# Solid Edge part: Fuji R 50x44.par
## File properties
Title: Lines R 50x44
Author: DESYS
Template: Parte SCARABEO.par
Last saved by: i.fialdini
Revision: 24
Application: Solid Edge
Tipo di contenuto documento: 0
Precisione: 0.990
Document Number: 6003
Revision: 0
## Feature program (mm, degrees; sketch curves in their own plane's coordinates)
sketch for "unnamed Protrusion 1" plane through (0, 0, 0) normal (0, -1, 0) x-axis (1, 0, 0)
extrude "unnamed Protrusion 1" add finite 140 along -normal
fillet "Rotondo_22" radius 35
lofted cutout "unnamed LoftedCutout 1"
sketch for "unnamed Protrusion 2" plane through (0, 140, 0) normal (0, 1, 0) x-axis (-1, 0, 0)
extrude "unnamed Protrusion 2" add through along -normal
draft "Spoglia_2"  Angles1 = 10 deg
fillet "Rotondo_46" radius 90
fillet "Rotondo_48" radius 5
fillet "Rotondo_50" radius 20
sketch for "unnamed Cutout 1" plane through (0, 0, 0) normal (0, -1, 0) x-axis (-1, 0, 0)
  line (-210, -62.5) -> (-210, -160)
  arc centre (-175, -160) radius 35 from (-175, -195) to (-210, -160) cw
  line (-175, -195) -> (175, -195)
  arc centre (175, -160) radius 35 from (210, -160) to (175, -195) cw
  line (210, -160) -> (210, 140)
  arc centre (175, 140) radius 35 from (175, 175) to (210, 140) cw
  line (175, 175) -> (-175, 175)
  arc centre (-175, 140) radius 35 from (-210, 140) to (-175, 175) cw
  line (-210, 140) -> (-210, 57.5)
  line (-210, 57.5) -> (-218.6603, 42.5)
  line (-218.6603, 42.5) -> (-218.6603, -47.5)
  line (-218.6603, -47.5) -> (-210, -62.5)
  dimension (linear) = 210
  dimension (linear) = 210
  dimension (linear) = 218.6603
extrude "unnamed Cutout 1" cut along +normal
fillet "Rotondo_51" radius 20
fillet "Rotondo_27" radius 10
sketch for "unnamed Protrusion 3" plane through (0, 25, 0) normal (0, -1, 0) x-axis (0, 0, -1)
extrude "unnamed Protrusion 3" add to key point along +normal
sketch for "Foro_9" plane through (0, 45, 0) normal (0, 1, 0) x-axis (-1, 0, 0)
hole "Foro_9" diameter 50 through
sketch for "ProtrusioneEstrusa_8" plane through (0, 0, 0) normal (0, 0, 1) x-axis (1, 0, 0)
extrude "ProtrusioneEstrusa_8" add finite 50 symmetric
fillet "Rotondo_28" radius 10
fillet "Rotondo_29" radius 5
fillet "Rotondo_33" radius 10
fillet "Rotondo_34" radius 5
fillet "Rotondo_35" radius 5
sketch for "unnamed Cutout 2" plane through (0, 67.5, 220) normal (0, 0, 1) x-axis (1, 0, 0)
extrude "unnamed Cutout 2" cut through along -normal
fillet "Rotondo_36" radius 10
fillet "Rotondo_38" radius 5
sketch for "unnamed Cutout 3" #1 plane through (0, 67.5, 220) normal (0, 0, 1) x-axis (1, 0, 0)
sketch for "unnamed Cutout 3" #2 plane through (0, 67.5, 220) normal (0, 0, 1) x-axis (1, 0, 0)
extrude "unnamed Cutout 3" cut through along -normal
sketch for "Foro_10" plane through (0, 67.5, 220) normal (0, 0, 1) x-axis (1, 0, 0)
  hole centre (-200, 42.5) bore radius 7.5
hole "Foro_10" finite
sketch for "unnamed Hole 1" plane through (0, 67.5, 220) normal (0, 0, 1) x-axis (1, 0, 0)
hole "unnamed Hole 1" finite
pattern "unnamed Pattern 1" of "Foro_10", "unnamed Hole 1"
fillet "Rotondo_39" radius 5
sketch for "Foro_12" plane through (0, 140, 0) normal (0, 1, 0) x-axis (-1, 0, 0)
hole "Foro_12" diameter 36 through
fillet "Rotondo_49" radius 2
Other named dimensions: "SuperficieOffset_2": Distance = 20 mm
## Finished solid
Body 1: sheet body, 10 faces, 31 edges, 24 vertices.
  Faces by surface: blend 6, plane 2, cone 1, offset 1
  Edges by curve: intersection 17, circle 9, line 4, curve on surface 1
Body 2: solid body, 156 faces, 356 edges, 201 vertices.
  Faces by surface: cylinder 57, plane 32, blend 31, torus 28, sphere 4, cone 2, offset 1, spline 1
  Edges by curve: circle 161, line 119, intersection 75, curve on surface 1
Bounding box of the edges (mm; curved faces can reach further): 500.000 x 140.000 x 435.000, from (-250, 0, -215) to (250, 140, 220).
Cylindrical faces by radius (mm): R5 x21, R7.5 x2, R10 x16, R18 x1, R20 x4, R25 x1, R35 x11, R109.4231 x1
Conical faces (half-angle, radius in mm at the cone's reference point): 10 deg R25.3038 x2, 10 deg R45 x1
Toroidal faces (ring radius, tube radius in mm): R10 r5 x2, R10 r10 x2, R20 r2 x1, R25 r10 x4, R30 r5 x13, R30 r10 x2, R35 r10 x1, R40 r5 x1, R40.8045 r5 x1, R114.4231 r5 x1
Spherical faces by radius (mm): R5 x4
Planar faces by outward normal: +x 2, +y 4, +z 5, -x 4, -y 10, -z 3, oblique 4
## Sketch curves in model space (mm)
arc centre (0, 31.2658, -204.1392) radius 110 from (0, 45, -95) through (0, 108.0036, -125.3274) to (0, 140, -187.5)
arc centre (0, 31.2658, 204.1392) radius 110 from (0, 45, 95) through (0, 108.0036, 125.3274) to (0, 140, 187.5)
ellipse centre (0, 140, 0) radii 197.5, 187.5
arc centre (-212.5652, 20.9494, 0) radius 120 from (-95, 45, 0) through (-133.6338, 111.3365, 0) to (-197.5, 140, 0)
arc centre (212.5652, 20.9494, 0) radius 120 from (95, 45, 0) through (133.6338, 111.3365, 0) to (197.5, 140, 0)
circle centre (0, 45, 0) radius 95
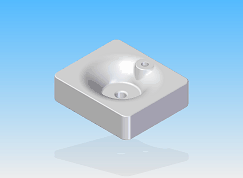
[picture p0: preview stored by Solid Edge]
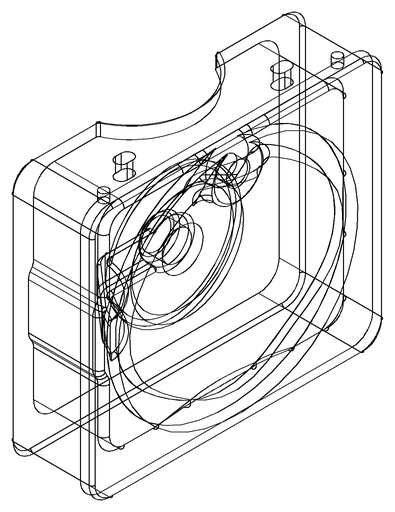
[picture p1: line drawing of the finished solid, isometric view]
